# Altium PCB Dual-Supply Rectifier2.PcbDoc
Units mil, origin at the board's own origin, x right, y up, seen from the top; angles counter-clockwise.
Board outline 2800 x 2200 mil, 2 copper layers (Top Layer, Bottom Layer); 35 components, 9 nets, 63 pads, 47 vias.
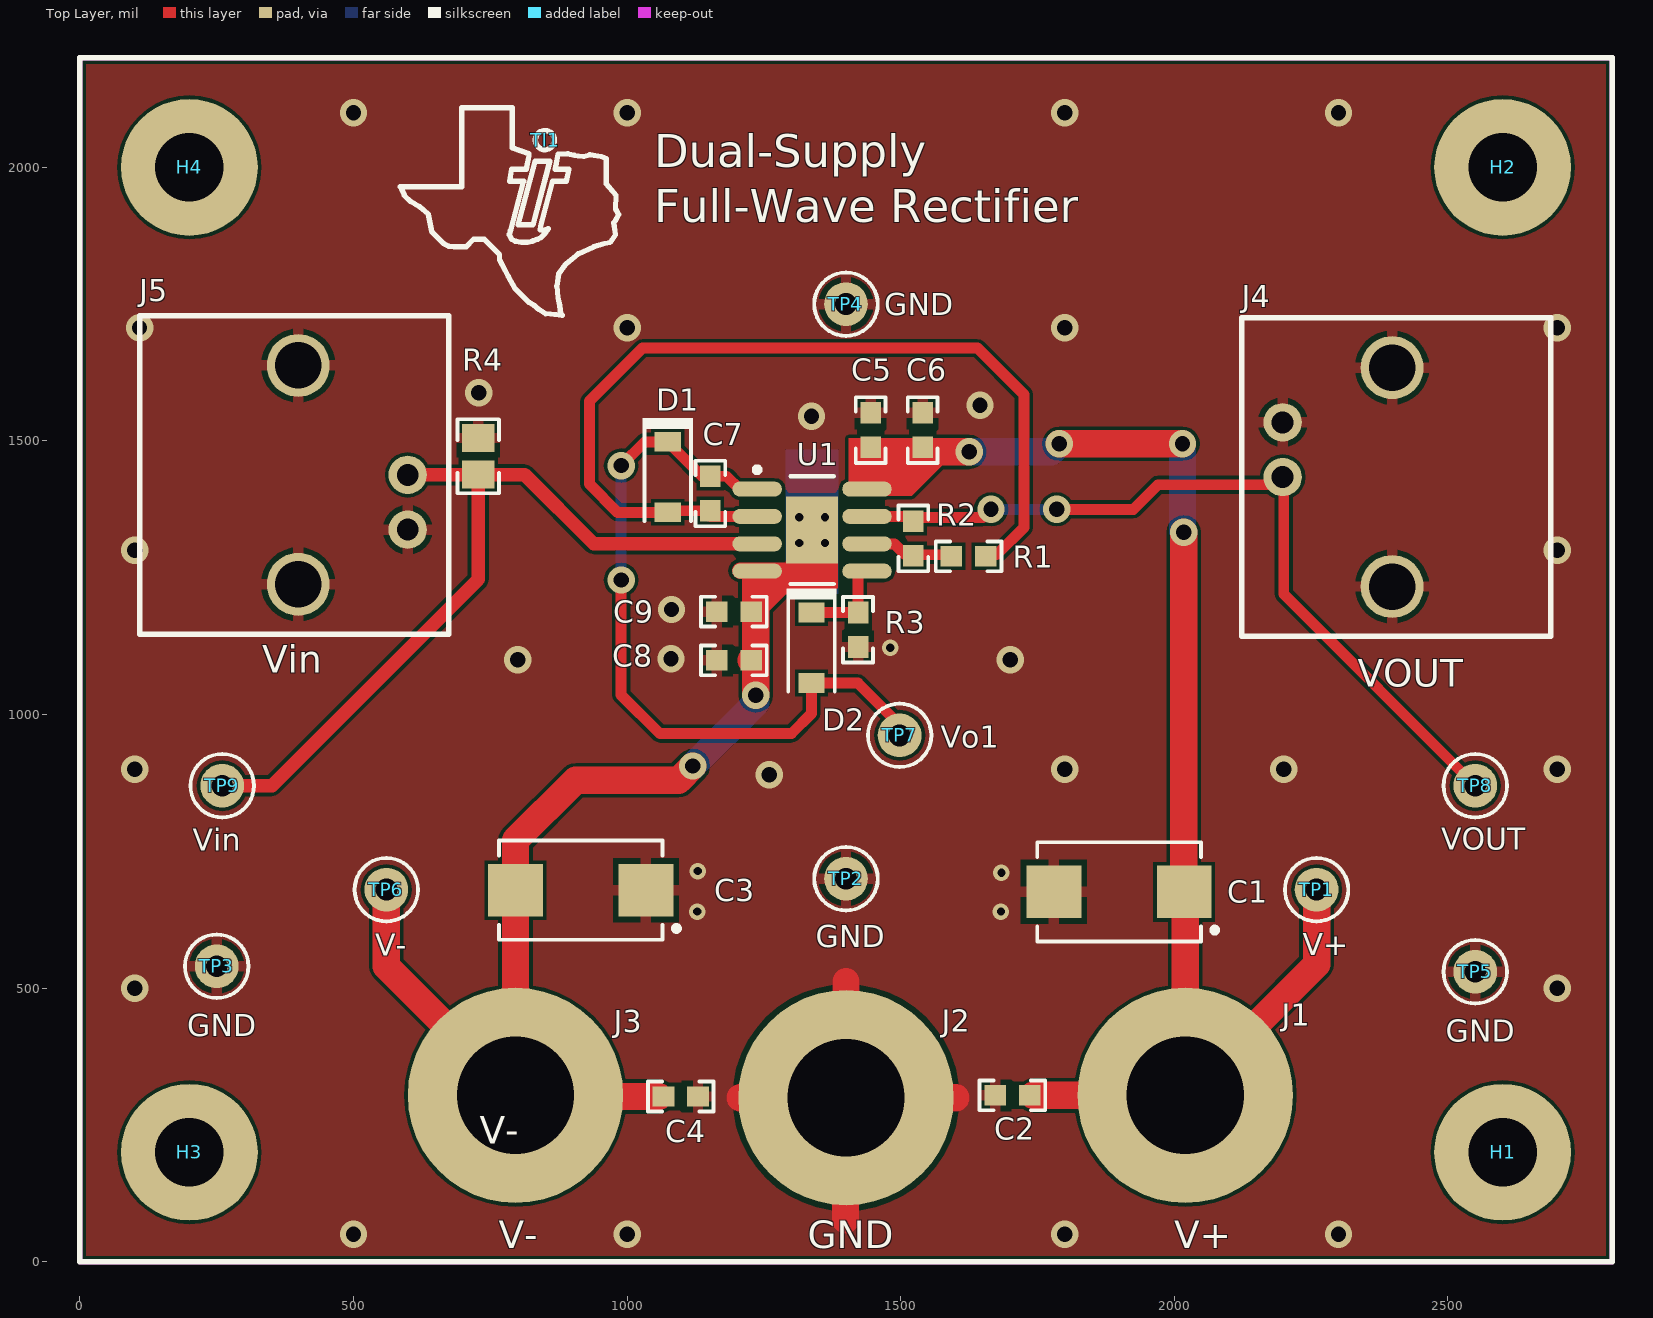
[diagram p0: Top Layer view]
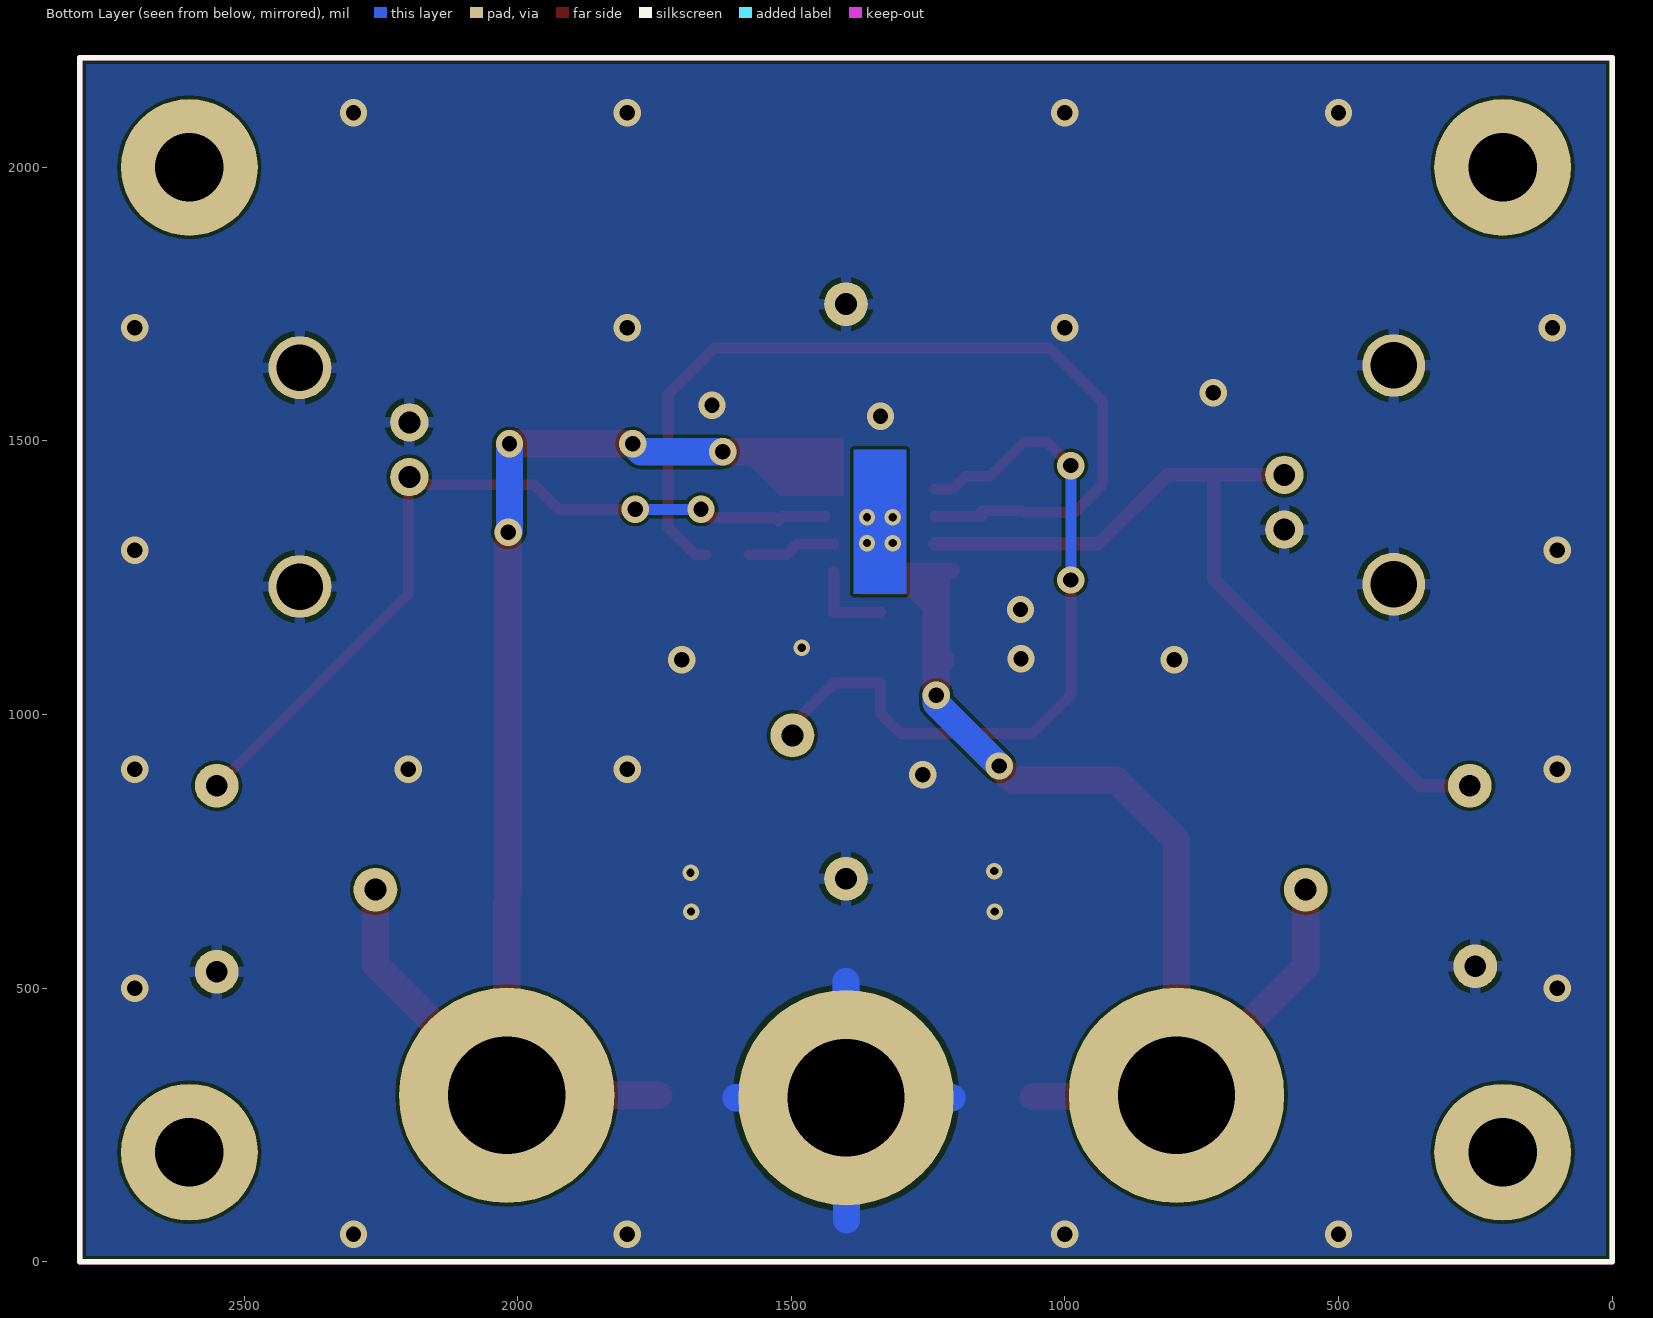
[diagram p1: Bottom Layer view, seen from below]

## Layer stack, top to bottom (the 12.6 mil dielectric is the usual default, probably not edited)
Top Layer: signal copper 1.4
Dielectric: dielectric 12.6, FR-4, Dk 4.8
Bottom Layer: signal copper 1.4

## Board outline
0,2200 2800,2200 2800,0 0,0 0,2200

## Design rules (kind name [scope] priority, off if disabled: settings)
Clearance [All] p1: gap=6
ComponentClearance ComponentClearance_1 [InComponent('TI1')] p1: gap=0 collisioncheckmode=3 verticalgap=0 showdistances=FALSE
ComponentClearance [All] p2: gap=10 collisioncheckmode=3 verticalgap=10 showdistances=FALSE
FabricationTestPointUsage TestPointUsage [All] p1: valid=0 allowmultiple=FALSE
FabricationTestpoint Testpoint [All] p1: side=3 testpointundercomponent=TRUE minsize=40 maxsize=100 preferedsize=60 minholesize=0 maxholesize=40 preferedholesize=32 testpointgrid=1 allowsidetop=TRUE allowsidebottom=TRUE usegrid=TRUE gridtolerance=0.01
HoleSize [All] p1: absolutevalues=TRUE maxlimit=246 minlimit=1 maxpercent=80.000 minpercent=20.000
PolygonConnect PolygonConnect_1 [(InComponentClass('All Components'))] p1: connectstyle=Relief reliefconductorwidth=20 reliefentries=4 polygonreliefangle="90 Angle" airgapwidth=10
PolygonConnect [All] p2: connectstyle=Direct reliefconductorwidth=25 reliefentries=4 polygonreliefangle="90 Angle" airgapwidth=10
RoutingVias [All] p1: holewidth=28 width=50 viastyle="Through Hole" minholewidth=28 minwidth=50 maxholewidth=28 maxwidth=50
SilkscreenOverComponentPads [All] p1: minsilkscreentomaskgap=10
SolderMaskExpansion [All] p1: expansion=4
Width [All] p1: maxlimit=100 minlimit=8 preferedwidth=15
23 further rules are at their usual default settings.

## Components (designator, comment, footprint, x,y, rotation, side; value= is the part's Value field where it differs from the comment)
C1 "TPSE106K050R0400" 7343-43 1899,676 r180 top
C2 "GRM188R72A104KA35D" 0603 1704,304 r180 top
C3 "TPSE106K050R0400" 7343-43 915.31,679 r180 top
C4 "GRM188R72A104KA35D" 0603 1098,302 r180 top
C5 "C1608C0G1H101J" 0603 1445,1520 r90 top
C6 "GRM188R72A104KA35D" 0603 1540,1520 r90 top
C7 "47P" 0603 1152,1404 r90 top
C8 "C1608C0G1H101J" 0603 1195.12,1099.05 r180 top
C9 "GRM188R72A104KA35D" 0603 1195.12,1188.05 r180 top
D1 "1N4148" SOD-123 1074,1434 r270 top
D2 "1N4148" SOD-123 1337,1122 r270 top
H1 "NA" "Mounting Hole" 2600,200 r0 top
H2 "NA" "Mounting Hole" 2600,2000 r0 top
H3 "NA" "Mounting Hole" 200,200 r0 top
H4 "NA" "Mounting Hole" 200,2000 r0 top
J1 "V+" Keystone_575-4 2020,304 r270 top
J2 "GND" Keystone_575-4 1400,300 r270 top
J3 "V-" Keystone_575-4 796,304 r270 top
J4 "1-1634612-0" "Right Angle BNC" 2198,1434 r270 top
J5 "1-1634612-0" "Right Angle BNC" 599,1438 r90 top
R1 "1KR" 0603 1624,1289 r0 top
R2 "1KR" 0603 1523,1322 r270 top
R3 "1kR" 0603 1422,1155 r90 top
R4 "49.9R" 0805 728,1472 r270 top
TI1 "Texas Instruments logo" "TI LOGO" 850,2050 r0 top
TP1 "V+" Keystone5000 2260,680 r90 top
TP2 "GND" Keystone5001 1400,700 r90 top
TP3 "GND" Keystone5001 250,540 r0 top
TP4 "GND" Keystone5001 1400,1750 r0 top
TP5 "GND" Keystone5001 2550,530 r0 top
TP6 "V-" Keystone5004 560,680 r270 top
TP7 "Vo1" Keystone5002 1498,962 r180 top
TP8 "VOUT" Keystone5002 2550,870 r270 top
TP9 "Vin" Keystone5002 260,870 r90 top
U1 "OPA2365" MRA08B_M 1338,1337.05 r0 top

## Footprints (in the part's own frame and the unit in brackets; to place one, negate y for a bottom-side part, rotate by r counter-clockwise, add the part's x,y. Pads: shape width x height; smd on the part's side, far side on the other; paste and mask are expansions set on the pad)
0603 [mm] "0603 from SM-752 data"
  rect 1x0.95 smd: 1(-0.8,0) 2(0.8,0)
  silkscreen extent -1.52,-0.69 1.52,0.69, body extent -0.87,-0.47 0.87,0.47, height 0.85
0805 [mm] "0805 from SM-752 data"
  rect 1.3x1.5 smd: 1(-0.85,0) 2(0.85,0)
  silkscreen extent -1.72,-0.97 1.72,0.97, body extent -1.1,-0.72 1.1,0.72, height 1.1
7343-43 [mm] "Medium density IPC based on Kemet T495 series"
  rect 2.55x2.45 smd: 1(-3.025,0) 2(3.025,0)
  silkscreen extent -4.56,-2.3 3.8,2.3, body extent -3.8,-2.3 3.8,2.3, height 4.3
Keystone5000 [mil] "For Keystone 500x miniature loop terminals"
  round 80 hole 40: 1(0,0)
  silkscreen extent -58,-58 58,58, body extent -49,-49 49,49, height 182
Keystone5001 [mil] "For Keystone 500x miniature loop terminals"
  round 80 hole 40: 1(0,0)
  silkscreen extent -58,-58 58,58, body extent -49,-49 49,49, height 182
Keystone5002 [mil] "For Keystone 500x miniature loop terminals"
  round 80 hole 40: 1(0,0)
  silkscreen extent -58,-58 58,58, body extent -49,-49 49,49, height 182
Keystone5004 [mil] "For Keystone 500x miniature loop terminals"
  round 80 hole 40: 1(0,0)
  silkscreen extent -58,-58 58,58, body extent -49,-49 49,49, height 182
Keystone_575-4 [mm] "Banana Jack"
  round 10 hole 5.45: 1(0,0)
  body extent -3.95,-3.95 3.92,3.93, height 2.36
"Mounting Hole" [mil]
  round 250 hole 125: 1(0,0)
MRA08B_M [mm] "SOIC, 8-Leads, Body 4.9x3.9mm, Pitch 1.27mm, Exposed Pad, IPC Low Density"
  oval 2.3x0.7 smd: 1(-2.55,1.905) 2(-2.55,0.635) 3(-2.55,-0.635) 4(-2.55,-1.905) 5(2.55,-1.905) 6(2.55,-0.635) 7(2.55,0.635) 8(2.55,1.905)
  rect 2.4x3.1 smd: 9(0,0)
  silkscreen extent -2.67,-2.5 1,2.93, body extent -2,-2.5 2,2.5, height 1.68
"Right Angle BNC" [mil]
  round 70 hole 40: 1(0,0) 2(-100,0)
  round 115 hole 85: 3(200,200) 4(-200,200)
  silkscreen extent -291,-75 291,490, body extent -290,-50 291,1325, height 519
SOD-123 [mm] "On Semi recommended land pattern"
  rect 0.915x1.22 smd: 1(-1.638,0) 2(1.638,0)
  silkscreen extent -2.74,-1.17 2.03,1.17, body extent -1.93,-0.9 1.93,0.9, height 1.35
"TI LOGO" [mil] "TI BUG"
  silkscreen extent -264,-320 135,59

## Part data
C1 C3: "CAP, TANT, 10uF, 50V, +/-10%, 0.4 ohm, 7343-43 SMD"
C2 C4 C6 C9: "CAP, CERM, 0.1uF, 100V, +/-10%, X7R, 0603"
C5 C8: "CAP, CERM, 100pF, 50V, +/-5%, C0G/NP0, 0603"
C7: library part C0603C470J5GACTU, "CAP, CERM, 47pF, 50V, +/-5%, C0G/NP0, 0603"
D1 D2: library part 1N4148W-7-F, "Diode, Ultrafast, 100V, 0.15A, SOD-123"
H1 H2 H3 H4: library part "Mounting Hole", "Mounting Hole"
J1 J2 J3: library part 575-4, "Standard Banana Jack, Uninsulated, 5.5mm"
J4 J5: library part "BNC Right Angle", "Right Angle BNC Connector"
R1 R2: library part RT0603BRD071KL, "RES, 1.00k ohm, 0.1%, 0.1W, 0603"
R3: library part RC0603FR-071KL, "RES, 1.00k ohm, 1%, 0.1W, 0603"
R4: library part CRCW080549R9FKEA, "RES, 49.9 ohm, 1%, 0.125W, 0805"
TI1: library part "TI LOGO", "TI BUG"
TP1: library part 5000, "Test Point, TH, Miniature, Red"
TP2 TP3 TP4 TP5: library part 5001, "Test Point, TH, Miniature, Black"
TP6: library part 5004, "Test Point, TH, Miniature, Yellow"
TP7 TP8 TP9: library part 5002, "Test Point, TH, Miniature, White"
U1: library part LF353M, "IC OPAMP GP R-R 50MHZ DUAL 8SOIC"

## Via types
v1: diameter 50, hole 28, Top Layer to Bottom Layer, 38 vias
v2: diameter 30, hole 15, Top Layer to Bottom Layer, 5 vias
v3: diameter 30, hole 15, Top Layer to Bottom Layer, tented top, 4 vias

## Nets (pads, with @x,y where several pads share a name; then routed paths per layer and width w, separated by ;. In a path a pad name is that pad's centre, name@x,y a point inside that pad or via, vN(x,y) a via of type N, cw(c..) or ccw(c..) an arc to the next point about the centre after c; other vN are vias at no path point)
GND: C1.2 C2.2 C3.1 C4.1 C5.2 C6.2 C8.2 C9.2 J2.1 J4.2 J4.3 J4.4 J5.2 J5.3 J5.4 R3.1 R4.1 TP2.1 TP3.1 TP4.1 TP5.1 | length 1618
  Top Layer w50: J2.1@1207,300 J2.1 ; 1399,77 J2.1@1399,280 ; 1400,512 J2.1 ; 1601,300 J2.1
  Bottom Layer w50: J2.1@1207,300 J2.1 ; 1399,77 J2.1@1399,280 ; 1400,512 J2.1 ; 1601,300 J2.1
  other v1: 500,50 1000,50 1800,50 2300,50 100,500 2700,500 1260,890 100,900 1800,900 2200,900 2700,900 800,1100 1700,1100 1080.12,1102.05 1081.12,1192.05 100,1300 2700,1300 1337,1545 1645,1565 729,1588 109,1707 1000,1707 1800,1707 2700,1707 500,2100 1000,2100 1800,2100 2300,2100
  other v2: 1128,640 1683,640 1684,711 1129,714 1481,1122
NetC7_1: C7.1 D1.2 R1.2 U1.2 | length 1684.1
  Top Layer w20: C7.1@1151.62,1362.05 U1.2 ; C7.1 1076.97,1372.5 D1.2 982.47,1369.53 931,1421 931,1573 1028,1670 1640,1670 1725,1585 1725,1341.99 1675.07,1292.05 R1.2@1655.5,1292.05
NetC7_2: C7.2 D1.1 D2.2 TP7.1 U1.1 | length 1365.9
  Top Layer w20: v1(989,1246) 989,1036 1060,965 1300,965 1337,1002 D2.2 1421.53,1057.53 TP7.1@1500.53,978.53 ; v1(989,1455) 1032.47,1498.47 D1.1 1136.97,1435.5 C7.2 1181.7,1435.5 1205.15,1412.05 U1.1
  Bottom Layer w20: v1(989,1246) v1(989,1455)
NetD2_1: D2.1 R3.2 U1.5 | length 159.9
  Top Layer w20: D2.1 R3.2 U1.5@1422,1261.41
NetJ4_1: J4.1 R2.1 TP8.1 U1.7 | length 1490.1
  Top Layer w20: U1.7 1514.44,1362.05 R2.1 1529.5,1360 1650,1360 v1(1665,1375) ; v1(1785,1375) 1925,1375 1970,1420 2184,1420 J4.1@2197,1433 ; J4.1@2200,1420 2200,1220 TP8.1
  Bottom Layer w20: v1(1665,1375) v1(1785,1375)
NetJ5_1: J5.1 R4.2 TP9.1 U1.3 | length 1506.9
  Top Layer w25: TP9.1 351,870 728,1247 R4.2 ; J5.1 727.46,1438 R4.2 ; U1.3 938.95,1312.05 812.46,1438.54 R4.2
NetR1_1: R1.1 R2.2 U1.6 | length 163.3
  Top Layer w20: U1.6@1422.64,1312.05 1488.63,1312.05 1508.12,1292.56 1508.63,1292.05 R1.1@1577.63,1292.05
V+: C1.1 C2.1 C5.1 C6.1 J1.1 TP1.1 U1.8 | length 2407.5
  Top Layer w50: C6.1@1540,1480 v1(1625,1480) ; C2.1@1742.5,304 J1.1 ; v1(1790,1495) v1(2015,1495) ; v1(2017,1333) 2017,677.09 C1.1 ; C1.1@2020,657.1 J1.1 ; TP1.1 2260,544 J1.1
  Bottom Layer w50: v1(1625,1480) 1775,1480 v1(1790,1495) ; v1(2015,1495) 2015,1335 v1(2017,1333)
V-: C3.2 C4.2 C8.1 C9.1 J3.1 TP6.1 U1.4 U1.9 | length 2129.9
  Top Layer w25: 1309,1262.57 1314.05,1263.05 U1.9@1338,1287
  Top Layer w30: U1.4@1206.61,1263.05 1309,1262.57
  Top Layer w50: TP6.1 560,540 J3.1 ; J3.1@775.69,306.57 J3.1@775.69,307.12 ; C4.2@1058,302 798,302 J3.1 ; v1(1120,906) 1094,880 906,880 796,770 J3.1 ; C8.1 1235,1090.67 v1(1235,1035) ; C8.1@1235.13,1099.05 C9.1@1235.13,1188.05 ; C9.1@1235.26,1177.02 U1.4@1235.26,1249
  Bottom Layer w50: v1(1120,906) 1235,1021 v1(1235,1035)
  other v3: 1314.38,1313.43 1361.62,1313.43 1314.38,1360.67 1361.62,1360.67
pads on no net: H1.1 H2.1 H3.1 H4.1

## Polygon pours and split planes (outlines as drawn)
GND on Top Layer "Top_GND" (solid, remove dead copper, pour order 4): 0,2200 2800,2200 2800,0 0,0 0,2200
GND on Bottom Layer "Bottom_GND" (solid, remove dead copper, pour order 6): 0,2200 2800,2200 2800,0 0,0 0,2200

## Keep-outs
Keep-Out Layer:
  the board outline again, w10

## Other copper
Top Layer:
  region net V-: 1290,1280 1385,1280 1385,1232.18 1372.82,1220 1290,1220 1260,1190 1260,1175 1210,1175 1210,1255 1230,1275 1290,1275
  region net V+: 1405,1400 1405,1505 1575,1505 1575,1455 1520,1400
Bottom Layer:
  region net V-: 1290,1484 1386,1484 1386,1221 1290,1221

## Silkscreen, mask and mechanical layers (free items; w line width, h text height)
Top Overlay:
  the board outline again, w10
  text "Dual-Supply" at 1050,2000 h60
  text "Full-Wave Rectifier" at 1050,1900 h60
  text "Vin" at 333,1076 h50
  text "VOUT" at 2335,1051 h50
  text "V-" at 730.69,216.02 h50
  text "V-" at 765,25 h50
  text "GND" at 1330,25 h50
  text "V+" at 2000,25 h50
Bottom Overlay:
  the board outline again, w10
Top Solder:
  the board outline again, w10
Bottom Solder:
  the board outline again, w10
